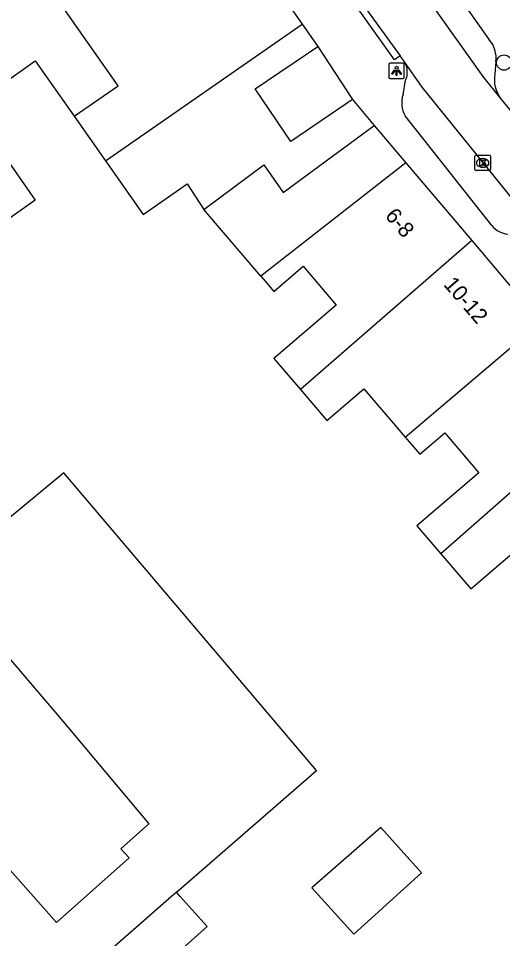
# Model space of a CAD drawing. Extents: x 160664 to 161506, y 382245 to 383288.
# Drawn here: x 160852.6 to 160883.8, y 383116.5 to 383175.8 of the extents above; entities that cross this region are included whole.
import ezdxf

# ---------------------------------------------------------------- set-up
doc = ezdxf.new("R2010")
doc.units = 0
for name, color, linetype in [('IMGEO_Boom', 7, 'Continuous'), ('IMGEO_Kolk', 7, 'Continuous'), ('IMGEO_Lichtpunt', 7, 'Continuous'), ('IMGEO_Pand', 7, 'Continuous'), ('IMGEO_Pand_nummerreeks', 7, 'Continuous'), ('IMGEO_Rijbaan_lokaal_open', 7, 'Continuous'), ('IMGEO_Voetpad_open', 7, 'Continuous')]:
    doc.layers.add(name, color=color, linetype=linetype)

msp = doc.modelspace()

# ---------------------------------------------------------------- linework, layer by layer
at = {"layer": 'IMGEO_Boom'}
msp.add_circle((160883.899, 383172.912), 0.489, dxfattribs=at)
at = {"layer": 'IMGEO_Kolk'}
for p, q in [((160882.018, 383166.021), (160882.018, 383166.873)), ((160882.093, 383166.947), (160882.945, 383166.947)), ((160882.506, 383166.727), (160882.531, 383166.727)), ((160883.019, 383166.873), (160883.019, 383166.021)), ((160882.945, 383165.947), (160882.093, 383165.947)), ((160882.529, 383166.167), (160882.504, 383166.167))]:
    msp.add_line(p, q, dxfattribs=at)
for points in [[(160882.018, 383166.021), (160882.018, 383166.873)], [(160882.093, 383166.947), (160882.945, 383166.947)], [(160882.339, 383166.647), (160882.462, 383166.647), (160882.462, 383166.496), (160882.592, 383166.647), (160882.756, 383166.647), (160882.61, 383166.496), (160882.763, 383166.247), (160882.611, 383166.247), (160882.526, 383166.411), (160882.462, 383166.344), (160882.462, 383166.247), (160882.339, 383166.247), (160882.339, 383166.647)], [(160883.019, 383166.873), (160883.019, 383166.021)], [(160882.945, 383165.947), (160882.093, 383165.947)]]:
    msp.add_lwpolyline(points, dxfattribs=at)
for centre, start, end in [((160882.095, 383166.871), 91.55205, 178.44795), ((160882.095, 383166.871), 91.55205, 178.44795), ((160882.943, 383166.871), 1.55205, 88.44795), ((160882.943, 383166.871), 1.55205, 88.44795), ((160882.095, 383166.023), 181.55205, 268.44795), ((160882.095, 383166.023), 181.55205, 268.44795), ((160882.943, 383166.023), 271.55205, 358.44795), ((160882.943, 383166.023), 271.55205, 358.44795)]:
    msp.add_arc(centre, 0.0765, start, end, dxfattribs=at)
for centre, major_axis, ratio, start_param, end_param in [((160882.505, 383166.447), (-0.387, 0.002), 0.722429, 4.712389, 7.853982), ((160882.53, 383166.447), (-0.39, 0.002), 0.717154, 1.570796, 4.712389)]:
    msp.add_ellipse(centre, major_axis=major_axis, ratio=ratio, start_param=start_param, end_param=end_param, dxfattribs=at)
at = {"layer": 'IMGEO_Lichtpunt'}
for p, q in [((160876.467, 383172.779), (160876.467, 383171.972)), ((160876.467, 383172.779), (160876.467, 383171.972)), ((160877.369, 383172.874), (160876.561, 383172.874)), ((160877.369, 383172.874), (160876.561, 383172.874)), ((160877.463, 383171.972), (160877.463, 383172.779)), ((160877.463, 383171.972), (160877.463, 383172.779)), ((160876.561, 383171.878), (160877.369, 383171.878)), ((160876.561, 383171.878), (160877.369, 383171.878))]:
    msp.add_line(p, q, dxfattribs=at)
for points in [[(160876.841, 383172.443), (160876.88, 383172.415), (160876.692, 383172.153), (160876.654, 383172.18), (160876.841, 383172.443)], [(160876.943, 383172.395), (160876.99, 383172.395), (160876.99, 383172.073), (160876.943, 383172.073), (160876.943, 383172.395)], [(160877.053, 383172.415), (160877.091, 383172.442), (160877.278, 383172.18), (160877.239, 383172.152), (160877.053, 383172.415)]]:
    msp.add_lwpolyline(points, dxfattribs=at)
msp.add_circle((160876.966, 383172.577), 0.0994, dxfattribs=at)
for centre, start, end in [((160876.561, 383172.779), 90, 180), ((160876.561, 383172.779), 90, 180), ((160877.369, 383172.779), 0, 90), ((160877.369, 383172.779), 0, 90), ((160876.561, 383171.972), 180, 270), ((160876.561, 383171.972), 180, 270), ((160877.369, 383171.972), 270, 0), ((160877.369, 383171.972), 270, 360)]:
    msp.add_arc(centre, 0.0946, start, end, dxfattribs=at)
at = {"layer": 'IMGEO_Pand'}
for points in [[(160861.86, 383188.217), (160870.875, 383175.395)], [(160856.165, 383169.45), (160859.003, 383171.423), (160851.374, 383182.272)], [(160858.185, 383166.581), (160870.875, 383175.395)], [(160870.875, 383175.395), (160871.892, 383173.948)], [(160874.133, 383170.526), (160870.145, 383167.831), (160867.855, 383171.22), (160871.892, 383173.948)], [(160851.626, 383171.582), (160853.654, 383173.016), (160856.165, 383169.45)], [(160851.626, 383171.582), (160849.457, 383170.048), (160853.653, 383164.052), (160850.814, 383162.057)], [(160874.133, 383170.526), (160875.522, 383168.848)], [(160856.165, 383169.45), (160858.185, 383166.581)], [(160864.538, 383163.451), (160868.402, 383166.312), (160869.648, 383164.54), (160875.522, 383168.848)], [(160875.522, 383168.848), (160877.565, 383166.443)], [(160858.185, 383166.581), (160860.627, 383163.112), (160863.466, 383165.09), (160864.538, 383163.451)], [(160877.565, 383166.443), (160868.204, 383159.152)], [(160877.565, 383166.443), (160881.82, 383161.435)], [(160868.204, 383159.152), (160864.538, 383163.451)], [(160881.82, 383161.435), (160870.765, 383151.833)], [(160881.82, 383161.435), (160884.486, 383158.297), (160884.595, 383158.39), (160884.871, 383158.068), (160884.767, 383157.979), (160885.378, 383157.265), (160885.51, 383157.378), (160885.813, 383157.023), (160885.706, 383156.931), (160886.307, 383156.228)], [(160868.204, 383159.152), (160868.487, 383158.821), (160869.048, 383158.165), (160870.938, 383159.781), (160873.071, 383157.287), (160869.045, 383153.843), (160870.765, 383151.833)], [(160877.516, 383148.781), (160886.307, 383156.228)], [(160870.765, 383151.833), (160872.462, 383149.849), (160874.848, 383151.89), (160877.516, 383148.781)], [(160890.838, 383150.912), (160879.818, 383141.245)], [(160877.516, 383148.781), (160878.47, 383147.669), (160880.076, 383149.056), (160880.301, 383148.793), (160882.282, 383146.477), (160878.274, 383143.05), (160879.818, 383141.245)], [(160862.78, 383119.438), (160871.792, 383127.293), (160855.494, 383146.477), (160849.437, 383141.466), (160847.865, 383143.697)], [(160879.818, 383141.245), (160881.749, 383138.988), (160885.78, 383142.436), (160887.628, 383140.276), (160885.986, 383138.872), (160886.895, 383137.81), (160888.536, 383139.214), (160891.861, 383142.058), (160895.66, 383145.307)], [(160838.066, 383123.41), (160841.544, 383126.254), (160851.849, 383134.678), (160855.448, 383130.467), (160860.986, 383123.842), (160859.189, 383122.242), (160859.707, 383121.66), (160855.036, 383117.501), (160850.542, 383122.549), (160847.23, 383119.601), (160844.049, 383123.372), (160840.66, 383120.426)], [(160875.961, 383123.617), (160871.506, 383119.731), (160874.2, 383116.746), (160878.565, 383120.684), (160875.961, 383123.617)], [(160862.78, 383119.438), (160850.763, 383108.963)], [(160863.37, 383112.275), (160861.516, 383114.358), (160864.744, 383117.232), (160863.018, 383119.171), (160862.78, 383119.438)]]:
    msp.add_lwpolyline(points, dxfattribs=at)
at = {"layer": 'IMGEO_Rijbaan_lokaal_open'}
for points in [[(160868.41, 383191.859), (160882.534, 383172.02), (160883.679, 383170.601)], [(160874.8, 383176.645), (160877.188, 383173.351)], [(160877.474, 383172.957), (160877.188, 383173.351)], [(160886.809, 383161.208), (160878.623, 383171.333), (160877.474, 383172.957)], [(160883.679, 383170.601), (160885.111, 383168.826)]]:
    msp.add_lwpolyline(points, dxfattribs=at)
at = {"layer": 'IMGEO_Voetpad_open'}
for points in [[(160871.736, 383190.331), (160877.264, 383182.408), (160882.945, 383174.384)], [(160877.188, 383173.351), (160876.824, 383173.096), (160874.496, 383176.386), (160874.8, 383176.645)], [(160871.892, 383173.948), (160874.133, 383170.526)], [(160883.37, 383172.977), (160883.297, 383172.164)], [(160877.386, 383170.844), (160877.547, 383171.772)], [(160883.119, 383162.402), (160877.518, 383169.486)]]:
    msp.add_lwpolyline(points, dxfattribs=at)
for centre, radius, start, end in [((160881.623, 383173.217), 1.764, 352.18433, 41.43072), ((160876.394, 383172.296), 1.266, 335.56183, 31.48848), ((160885.354, 383171.839), 2.083, 171.01123, 216.45669), ((160878.947, 383170.31), 1.65, 161.12485, 209.97877), ((160884.312, 383163.384), 1.545, 219.44059, 263.97116)]:
    msp.add_arc(centre, radius, start, end, dxfattribs=at)

# ---------------------------------------------------------------- texts
at = {"layer": 'IMGEO_Pand_nummerreeks'}
for s, rotation, p in [('6-8', 310.35126, (160876.177, 383163.011)), ('10-12', 310.75428, (160879.948, 383158.582))]:
    msp.add_text(s, height=1, rotation=rotation, dxfattribs=at).set_placement(p)

doc.saveas('drawing.dxf')
